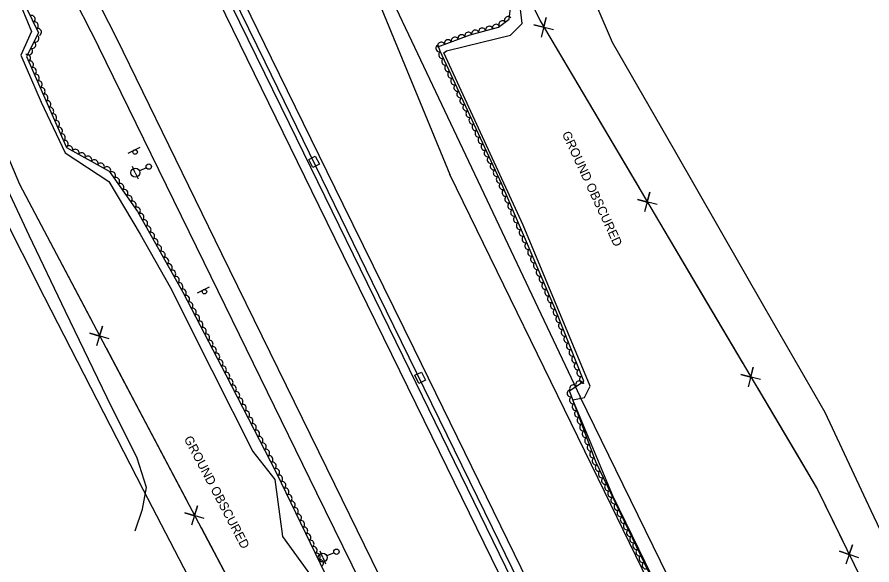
# Model space of a CAD drawing. Extents: x 1746719 to 1766531, y 631721 to 662391.
# Drawn here: x 1762199.7 to 1762673.2, y 637330.1 to 637633.4 of the extents above; entities that cross this region are included whole.
import ezdxf

# ---------------------------------------------------------------- set-up
doc = ezdxf.new("R2010")
doc.units = 0
for name, color, linetype in [('SURVEY - AERIAL SURVEY - Photo Control - Points - Elevations', 7, 'Continuous'), ('SURVEY - AERIAL SURVEY - Photo Control - Points - Locators', 7, 'Continuous'), ('SURVEY - AERIAL SURVEY - Photo Control - Points - Numbers', 7, 'Continuous'), ('SURVEY - AERIAL SURVEY - Photo Control with Text', 7, 'Continuous'), ('SURVEY - CENTERLINE - Existing Roads - Development', 7, 'Continuous'), ('SURVEY - CENTERLINE - Existing Roads Curve Text', 7, 'Continuous'), ('SURVEY - CENTERLINE - Preliminary Curve Text', 7, 'Continuous'), ('SURVEY - CONTROL - Grid', 7, 'Continuous')]:
    doc.layers.add(name, color=color, linetype=linetype)

msp = doc.modelspace()

# ---------------------------------------------------------------- linework, layer by layer
at = {"layer": 'SURVEY - AERIAL SURVEY - Photo Control - Points - Elevations'}
for points in [[(1762199.06, 638166.32), (1762211.4, 638121.29), (1762232.94, 638059.11), (1762264.35, 637979.74), (1762303.34, 637883.11), (1762331.77, 637813.41), (1762357.94, 637747.45), (1762511.67, 637423.21)], [(1762192.08, 638161.63), (1762201.41, 638132.06), (1762213.6, 638099.63), (1762234.5, 638048.54), (1762261.83, 637980.82), (1762283.63, 637927.14), (1762314.42, 637851.17), (1762341.55, 637783.76), (1762439.45, 637546.18)], [(1762773.06, 636698.72), (1762724.62, 636797.23), (1762665.78, 636917.21), (1762608.96, 637033.7), (1762547.76, 637159.19), (1762483.24, 637291.54), (1762429.61, 637401.09), (1762367.13, 637528.71), (1762311.22, 637643.03), (1762248.83, 637770.86), (1762183.89, 637904.12), (1762125.15, 638021.3), (1762090.32, 638088.89)], [(1762034.93, 638049.02), (1762054.49, 638012.9), (1762105.98, 637910.8), (1762134.93, 637855.15), (1762202.15, 637724.88), (1762254.87, 637621.71)], [(1762025.26, 638043.78), (1762044.74, 638007.8), (1762096.19, 637905.79), (1762125.16, 637850.09), (1762192.36, 637719.86), (1762245.07, 637616.7)], [(1762783.5, 636705.24), (1762745.76, 636781.92), (1762702.74, 636870.15), (1762649.08, 636980.15), (1762603.69, 637072.36), (1762560.73, 637160.61), (1762512.91, 637258.85), (1762467.62, 637351.57), (1762419.77, 637449.66), (1762380.4, 637529.73), (1762340.69, 637610.68), (1762307.07, 637679.74), (1762272.3, 637751.43), (1762238.92, 637822.21), (1762204.21, 637890.89), (1762159.32, 637981.97)], [(1762719.21, 636672.25), (1762670.76, 636770.78), (1762611.89, 636890.84), (1762555.03, 637007.4), (1762493.83, 637132.9), (1762429.32, 637265.2), (1762375.72, 637374.71), (1762313.23, 637502.34), (1762254.75, 637621.92)], [(1762709.34, 636667.39), (1762660.89, 636765.94), (1762602, 636886.01), (1762545.14, 637002.58), (1762483.94, 637128.07), (1762419.44, 637260.37), (1762365.84, 637369.88), (1762303.35, 637497.51), (1762244.87, 637617.09)], [(1762837.34, 636731.73), (1762799.64, 636808.32), (1762756.67, 636896.45), (1762702.96, 637006.55), (1762657.57, 637098.74), (1762614.67, 637186.87), (1762566.84, 637285.15), (1762521.54, 637377.89), (1762439.45, 637546.18)], [(1762265.09, 637348.99), (1762269.25, 637361.06), (1762271.47, 637373.04), (1762266.29, 637389.23), (1762249.68, 637422.68), (1762226.47, 637470.48), (1762206.48, 637512.4), (1762193.37, 637540.54), (1762180.37, 637534.66)], [(1762847.2, 636736.59), (1762809.52, 636813.16), (1762766.56, 636901.27), (1762712.84, 637011.39), (1762667.45, 637103.58), (1762624.57, 637191.68), (1762576.73, 637289.97), (1762531.42, 637382.71), (1762511.67, 637423.21)]]:
    msp.add_lwpolyline(points, dxfattribs=at)
at = {"layer": 'SURVEY - AERIAL SURVEY - Photo Control - Points - Locators'}
for points in [[(1762326.67, 637262), (1762269.77, 637371.55), (1762214.91, 637478.27), (1762165.66, 637575.86), (1762098.38, 637709.46), (1762055.59, 637808.21), (1761992.6, 637953.19), (1761970, 638004.8), (1761965.61, 638018.7), (1762014.67, 638044.97)], [(1762576.32, 637272.96), (1762529.81, 637368.33), (1762507.54, 637421.48), (1762513.99, 637422.78), (1762517.13, 637429.14), (1762480.15, 637518.22), (1762436.08, 637613.66), (1762437.61, 637614.72), (1762448.18, 637617.32), (1762473.13, 637623.33), (1762479.48, 637629.78), (1762477.77, 637644.11), (1762489.41, 637650.03), (1762495.34, 637645.1), (1762494.82, 637700.01), (1762529.42, 637619.53), (1762563.68, 637559.91), (1762613.96, 637472.25), (1762647.24, 637414.63), (1762672.68, 637360.22), (1762723.14, 637253.78)], [(1762180.17, 637686.09), (1762199.83, 637644.82), (1762207.76, 637625.5), (1762201.9, 637612.39), (1762213.14, 637586.33), (1762226.46, 637558.16), (1762250.57, 637542.35), (1762267.92, 637513.28), (1762284.62, 637483.85), (1762307.59, 637437.87), (1762330.31, 637392.91), (1762342.46, 637377.46), (1762346.82, 637345.77), (1762363.21, 637323.07)]]:
    msp.add_lwpolyline(points, dxfattribs=at)
at = {"layer": 'SURVEY - AERIAL SURVEY - Photo Control - Points - Numbers'}
for points in [[(1762101.32, 638090.04), (1762139.47, 638013.18), (1762181.78, 637926.27), (1762216.4, 637854.87), (1762274.24, 637736.9), (1762337.04, 637608.61), (1762400, 637479.52), (1762462.92, 637350.83), (1762538.73, 637195.19), (1762608.95, 637051.84), (1762674.55, 636917.47), (1762724.06, 636816.01), (1762780.33, 636702.09)], [(1762777.65, 636700.23), (1762731.1, 636795.47), (1762662.3, 636936.22), (1762598.25, 637067), (1762540.66, 637184.6), (1762481.17, 637306.94), (1762413.68, 637445.44), (1762350.64, 637574.34), (1762291.14, 637695.72), (1762205.98, 637869.78), (1762138.69, 638007.58), (1762099.48, 638088.85)]]:
    msp.add_lwpolyline(points, dxfattribs=at)
at = {"layer": 'SURVEY - AERIAL SURVEY - Photo Control with Text'}
for points in [[(1762183.78, 637681.77), (1762211.55, 637624.74), (1762204.99, 637611.54), (1762227.04, 637561.12), (1762250.81, 637548.04), (1762266.45, 637525.73), (1762291.47, 637481.04), (1762315.33, 637435.3), (1762343.29, 637381.3), (1762378.31, 637308.67)], [(1762432.78, 637616.92), (1762450.69, 637623.52), (1762466.41, 637627.88), (1762472.25, 637632.27), (1762473.15, 637640.04), (1762474.87, 637644.8), (1762492.37, 637653.51), (1762520.6, 637649.82)], [(1762862.89, 636752.12), (1762849.55, 636763.36), (1762801.15, 636845.57), (1762772.64, 636891.97), (1762776.9, 636906.16), (1762740.47, 636971.71), (1762720.4, 636978.55), (1762714.68, 636989.42), (1762685.48, 637052.24), (1762704.87, 637065.85), (1762719.23, 637071.7), (1762707.91, 637099.34), (1762680.97, 637100.35), (1762662.78, 637097.23), (1762658.4, 637102.56), (1762612.3, 637197.08), (1762558.78, 637307.19), (1762520.33, 637387.23), (1762505.74, 637426.54), (1762513.58, 637431.76), (1762498.22, 637470.88), (1762468.27, 637540.9), (1762434.15, 637614.59), (1762433.01, 637617.65)]]:
    msp.add_lwpolyline(points, dxfattribs=at)
for centre, major_axis in [((1762207.85, 637632.34), (0.88, -1.8)), ((1762209.6, 637628.74), (0.88, -1.8)), ((1762468.49, 637629.44), (1.6, 1.2)), ((1762471.69, 637631.84), (1.6, 1.2)), ((1762211.35, 637625.15), (0.88, -1.8)), ((1762453.5, 637624.3), (1.93, 0.53)), ((1762457.35, 637625.37), (1.93, 0.53)), ((1762461.21, 637626.44), (1.93, 0.53)), ((1762465.06, 637627.5), (1.93, 0.53)), ((1762209.97, 637621.56), (-0.89, -1.79)), ((1762438.41, 637618.99), (1.88, 0.69)), ((1762442.17, 637620.38), (1.88, 0.69)), ((1762445.92, 637621.76), (1.88, 0.69)), ((1762449.67, 637623.15), (1.88, 0.69)), ((1762206.41, 637614.4), (-0.89, -1.79)), ((1762208.19, 637617.98), (-0.89, -1.79)), ((1762433.58, 637616.12), (-0.7, 1.87)), ((1762434.66, 637617.61), (1.88, 0.69)), ((1762205.31, 637610.8), (0.8, -1.83)), ((1762435.15, 637612.44), (-0.84, 1.81)), ((1762206.91, 637607.13), (0.8, -1.83)), ((1762436.83, 637608.81), (-0.84, 1.81)), ((1762438.51, 637605.18), (-0.84, 1.81)), ((1762208.52, 637603.47), (0.8, -1.83)), ((1762210.12, 637599.8), (0.8, -1.83)), ((1762440.19, 637601.55), (-0.84, 1.81)), ((1762211.72, 637596.14), (0.8, -1.83)), ((1762441.87, 637597.92), (-0.84, 1.81)), ((1762213.32, 637592.48), (0.8, -1.83)), ((1762443.55, 637594.29), (-0.84, 1.81)), ((1762445.23, 637590.66), (-0.84, 1.81)), ((1762214.93, 637588.81), (0.8, -1.83)), ((1762446.91, 637587.03), (-0.84, 1.81)), ((1762216.53, 637585.15), (0.8, -1.83)), ((1762218.13, 637581.48), (0.8, -1.83)), ((1762448.59, 637583.4), (-0.84, 1.81)), ((1762219.74, 637577.82), (0.8, -1.83)), ((1762450.27, 637579.77), (-0.84, 1.81)), ((1762221.34, 637574.15), (0.8, -1.83)), ((1762451.95, 637576.15), (-0.84, 1.81)), ((1762453.63, 637572.52), (-0.84, 1.81)), ((1762222.94, 637570.49), (0.8, -1.83)), ((1762224.54, 637566.82), (0.8, -1.83)), ((1762455.31, 637568.89), (-0.84, 1.81)), ((1762226.15, 637563.16), (0.8, -1.83)), ((1762456.99, 637565.26), (-0.84, 1.81)), ((1762228.6, 637560.26), (1.75, -0.96)), ((1762232.1, 637558.33), (1.75, -0.96)), ((1762458.68, 637561.63), (-0.84, 1.81)), ((1762460.36, 637558), (-0.84, 1.81)), ((1762235.6, 637556.41), (1.75, -0.96)), ((1762239.11, 637554.48), (1.75, -0.96)), ((1762242.61, 637552.55), (1.75, -0.96)), ((1762462.04, 637554.37), (-0.84, 1.81)), ((1762246.12, 637550.62), (1.75, -0.96)), ((1762249.62, 637548.69), (1.75, -0.96)), ((1762463.72, 637550.74), (-0.84, 1.81)), ((1762252.33, 637545.87), (1.15, -1.64)), ((1762465.4, 637547.11), (-0.84, 1.81)), ((1762467.08, 637543.48), (-0.84, 1.81)), ((1762254.62, 637542.6), (1.15, -1.64)), ((1762256.92, 637539.32), (1.15, -1.64)), ((1762468.73, 637539.83), (-0.79, 1.84)), ((1762259.22, 637536.05), (1.15, -1.64)), ((1762470.3, 637536.15), (-0.79, 1.84)), ((1762261.51, 637532.77), (1.15, -1.64)), ((1762263.81, 637529.5), (1.15, -1.64)), ((1762471.87, 637532.48), (-0.79, 1.84)), ((1762266.1, 637526.22), (1.15, -1.64)), ((1762473.45, 637528.8), (-0.79, 1.84)), ((1762475.02, 637525.12), (-0.79, 1.84)), ((1762268.11, 637522.76), (0.98, -1.75)), ((1762270.06, 637519.27), (0.98, -1.75)), ((1762476.59, 637521.44), (-0.79, 1.84)), ((1762272.02, 637515.78), (0.98, -1.75)), ((1762478.17, 637517.77), (-0.79, 1.84)), ((1762273.97, 637512.29), (0.98, -1.75)), ((1762479.74, 637514.09), (-0.79, 1.84)), ((1762481.31, 637510.41), (-0.79, 1.84)), ((1762275.92, 637508.8), (0.98, -1.75)), ((1762277.88, 637505.31), (0.98, -1.75)), ((1762482.89, 637506.73), (-0.79, 1.84)), ((1762279.83, 637501.82), (0.98, -1.75)), ((1762484.46, 637503.06), (-0.79, 1.84)), ((1762281.79, 637498.33), (0.98, -1.75)), ((1762486.03, 637499.38), (-0.79, 1.84)), ((1762283.74, 637494.84), (0.98, -1.75)), ((1762285.69, 637491.35), (0.98, -1.75)), ((1762487.61, 637495.7), (-0.79, 1.84)), ((1762489.18, 637492.02), (-0.79, 1.84)), ((1762287.65, 637487.86), (0.98, -1.75)), ((1762490.75, 637488.35), (-0.79, 1.84)), ((1762289.6, 637484.37), (0.98, -1.75)), ((1762492.32, 637484.67), (-0.79, 1.84)), ((1762291.55, 637480.88), (0.93, -1.77)), ((1762293.4, 637477.33), (0.93, -1.77)), ((1762493.9, 637480.99), (-0.79, 1.84)), ((1762495.47, 637477.31), (-0.79, 1.84)), ((1762295.25, 637473.78), (0.93, -1.77)), ((1762497.04, 637473.63), (-0.79, 1.84)), ((1762297.1, 637470.24), (0.93, -1.77)), ((1762498.59, 637469.95), (-0.73, 1.86)), ((1762298.95, 637466.69), (0.93, -1.77)), ((1762300.8, 637463.14), (0.93, -1.77)), ((1762500.05, 637466.22), (-0.73, 1.86)), ((1762302.65, 637459.6), (0.93, -1.77)), ((1762501.51, 637462.5), (-0.73, 1.86)), ((1762502.97, 637458.78), (-0.73, 1.86)), ((1762304.5, 637456.05), (0.93, -1.77)), ((1762504.44, 637455.05), (-0.73, 1.86)), ((1762306.36, 637452.51), (0.93, -1.77)), ((1762308.21, 637448.96), (0.93, -1.77)), ((1762505.9, 637451.33), (-0.73, 1.86)), ((1762310.06, 637445.41), (0.93, -1.77)), ((1762507.36, 637447.6), (-0.73, 1.86)), ((1762508.82, 637443.88), (-0.73, 1.86)), ((1762311.91, 637441.87), (0.93, -1.77)), ((1762510.28, 637440.16), (-0.73, 1.86)), ((1762313.76, 637438.32), (0.93, -1.77)), ((1762315.61, 637434.77), (0.92, -1.78)), ((1762511.74, 637436.43), (-0.73, 1.86)), ((1762317.45, 637431.22), (0.92, -1.78)), ((1762511.1, 637430.11), (1.66, 1.11)), ((1762513.2, 637432.71), (-0.73, 1.86)), ((1762319.28, 637427.67), (0.92, -1.78)), ((1762506.29, 637425.07), (-0.7, 1.88)), ((1762507.77, 637427.89), (1.66, 1.11)), ((1762321.12, 637424.12), (0.92, -1.78)), ((1762322.96, 637420.57), (0.92, -1.78)), ((1762507.68, 637421.32), (-0.7, 1.88)), ((1762324.8, 637417.01), (0.92, -1.78)), ((1762509.07, 637417.57), (-0.7, 1.88)), ((1762326.64, 637413.46), (0.92, -1.78)), ((1762510.46, 637413.82), (-0.7, 1.88)), ((1762328.48, 637409.91), (0.92, -1.78)), ((1762330.32, 637406.36), (0.92, -1.78)), ((1762511.86, 637410.07), (-0.7, 1.88)), ((1762513.25, 637406.32), (-0.7, 1.88)), ((1762332.16, 637402.81), (0.92, -1.78)), ((1762514.64, 637402.57), (-0.7, 1.88)), ((1762334, 637399.25), (0.92, -1.78)), ((1762516.03, 637398.82), (-0.7, 1.88)), ((1762335.84, 637395.7), (0.92, -1.78)), ((1762337.68, 637392.15), (0.92, -1.78)), ((1762517.42, 637395.07), (-0.7, 1.88)), ((1762339.52, 637388.6), (0.92, -1.78)), ((1762518.81, 637391.32), (-0.7, 1.88)), ((1762520.21, 637387.57), (-0.7, 1.88)), ((1762341.36, 637385.05), (0.92, -1.78)), ((1762521.91, 637383.95), (-0.87, 1.8)), ((1762343.19, 637381.49), (0.92, -1.78)), ((1762344.94, 637377.89), (0.87, -1.8)), ((1762523.64, 637380.35), (-0.87, 1.8)), ((1762346.67, 637374.29), (0.87, -1.8)), ((1762525.37, 637376.74), (-0.87, 1.8)), ((1762527.1, 637373.14), (-0.87, 1.8)), ((1762348.41, 637370.69), (0.87, -1.8)), ((1762528.83, 637369.53), (-0.87, 1.8)), ((1762350.15, 637367.08), (0.87, -1.8)), ((1762351.89, 637363.48), (0.87, -1.8)), ((1762530.57, 637365.93), (-0.87, 1.8)), ((1762353.62, 637359.88), (0.87, -1.8)), ((1762532.3, 637362.32), (-0.87, 1.8)), ((1762534.03, 637358.72), (-0.87, 1.8)), ((1762355.36, 637356.27), (0.87, -1.8)), ((1762535.76, 637355.11), (-0.87, 1.8)), ((1762357.1, 637352.67), (0.87, -1.8)), ((1762358.83, 637349.07), (0.87, -1.8)), ((1762537.49, 637351.5), (-0.87, 1.8)), ((1762360.57, 637345.46), (0.87, -1.8)), ((1762539.23, 637347.9), (-0.87, 1.8)), ((1762362.31, 637341.86), (0.87, -1.8)), ((1762540.96, 637344.29), (-0.87, 1.8)), ((1762542.69, 637340.69), (-0.87, 1.8)), ((1762364.04, 637338.26), (0.87, -1.8)), ((1762365.78, 637334.65), (0.87, -1.8)), ((1762544.42, 637337.08), (-0.87, 1.8)), ((1762367.52, 637331.05), (0.87, -1.8)), ((1762546.15, 637333.48), (-0.87, 1.8)), ((1762547.89, 637329.87), (-0.87, 1.8))]:
    msp.add_ellipse(centre, major_axis=major_axis, ratio=0.940188, start_param=0, end_param=3.141593, dxfattribs=at)
at = {"layer": 'SURVEY - CENTERLINE - Existing Roads - Development'}
for p, q in [((1762265.19, 637547.22), (1762263.64, 637550.63)), ((1762271.33, 637550.01), (1762267.46, 637548.25)), ((1762265.19, 637547.22), (1762266.74, 637543.8)), ((1762369.06, 637334.2), (1762367.6, 637337.65)), ((1762375.28, 637336.82), (1762371.37, 637335.17)), ((1762369.06, 637334.2), (1762370.52, 637330.74))]:
    msp.add_line(p, q, dxfattribs=at)
for centre, radius in [((1762272.7, 637550.63), 1.5), ((1762265.19, 637547.22), 2.5), ((1762376.66, 637337.41), 1.5), ((1762369.06, 637334.2), 2.5)]:
    msp.add_circle(centre, radius, dxfattribs=at)
at = {"layer": 'SURVEY - CENTERLINE - Existing Roads Curve Text'}
for points in [[(1762233.05, 638186.11), (1762232.15, 638176.06), (1762236.35, 638177.14), (1762242.98, 638144.89), (1762268.6, 638084.83), (1762295.55, 638028.9), (1762340.04, 637936.99), (1762382.83, 637849.97), (1762430.45, 637751.03), (1762470.02, 637671.11), (1762489.49, 637631.31), (1762643.02, 637371.95), (1762683.78, 637288.85), (1762709.82, 637235.07), (1762773.45, 637100.98), (1762849.07, 636951.78), (1762928.82, 636789.81)], [(1762015.64, 638032.17), (1762036.93, 637947.97), (1762071.82, 637841.31), (1762135.35, 637696.28), (1762201.09, 637540.86), (1762395.93, 637172.65)], [(1762496.92, 637626.42), (1762486.01, 637629.15), (1762491.49, 637627.74), (1762492.89, 637633.22), (1762490.03, 637622.35)], [(1762495.34, 637621.42), (1762518.98, 637581.49)], [(1762518.98, 637581.49), (1762544.45, 637538.47)], [(1762197.18, 637550.12), (1762201.09, 637540.86), (1762218.09, 637508.74)], [(1762554.23, 637529.61), (1762543.32, 637532.33), (1762548.8, 637530.93), (1762550.2, 637536.41), (1762547.34, 637525.54)], [(1762552.65, 637524.61), (1762576.29, 637484.69)], [(1762218.09, 637508.74), (1762241.48, 637464.54)], [(1762576.29, 637484.69), (1762601.76, 637441.66)], [(1762250.82, 637455.23), (1762240.05, 637458.47), (1762245.46, 637456.81), (1762247.12, 637462.21), (1762243.75, 637451.49)], [(1762249.01, 637450.31), (1762270.71, 637409.3)], [(1762611.53, 637432.8), (1762600.62, 637435.53), (1762606.1, 637434.12), (1762607.51, 637439.6), (1762604.65, 637428.73)], [(1762609.96, 637427.8), (1762633.6, 637387.88)], [(1762270.71, 637409.3), (1762294.09, 637365.11)], [(1762633.6, 637387.88), (1762643.02, 637371.95), (1762656.89, 637343.67)], [(1762303.43, 637355.79), (1762292.67, 637359.03), (1762298.07, 637357.37), (1762299.74, 637362.78), (1762296.36, 637352.05)], [(1762301.62, 637350.88), (1762323.32, 637309.86)], [(1762665.94, 637334.08), (1762655.28, 637337.65), (1762660.63, 637335.82), (1762662.46, 637341.17), (1762658.76, 637330.56)]]:
    msp.add_lwpolyline(points, dxfattribs=at)
at = {"layer": 'SURVEY - CENTERLINE - Preliminary Curve Text'}
for p, q in [((1762364.27, 637553.32), (1762364.27, 637553.32)), ((1762423, 637433.73), (1762423, 637433.73))]:
    msp.add_line(p, q, dxfattribs=at)
for points in [[(1762361.35, 637554.64), (1762364.92, 637556.45), (1762367.18, 637551.99), (1762363.61, 637550.18), (1762361.35, 637554.64)], [(1762420.1, 637435.09), (1762423.7, 637436.85), (1762425.9, 637432.36), (1762422.31, 637430.6), (1762420.1, 637435.09)]]:
    msp.add_lwpolyline(points, dxfattribs=at)
at = {"layer": 'SURVEY - CONTROL - Grid'}
for p, q in [((1762261.19, 637558.12), (1762267.91, 637561.44)), ((1762299.59, 637480.79), (1762306.32, 637484.11))]:
    msp.add_line(p, q, dxfattribs=at)
for centre in [(1762265.11, 637558.69), (1762303.52, 637481.36)]:
    msp.add_circle(centre, 1.25, dxfattribs=at)

# ---------------------------------------------------------------- texts
at = {"layer": 'SURVEY - AERIAL SURVEY - Photo Control - Points - Locators'}
for rotation, p in [(294.93, (1762501.41, 637568.8)), (297.7687, (1762292, 637399.95))]:
    msp.add_text('GROUND OBSCURED', height=5, rotation=rotation, dxfattribs=at).set_placement(p)

doc.saveas('drawing.dxf')
